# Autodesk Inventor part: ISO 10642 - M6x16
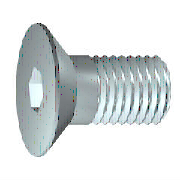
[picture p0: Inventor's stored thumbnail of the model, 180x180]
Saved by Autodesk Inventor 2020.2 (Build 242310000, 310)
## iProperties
Created: 2019-01
Part Number: ISO 10642 - M6x16
Material: Stahl, weich
Description: Senkschrauben mit Innensechskant
Document SubType Name: Modeling
Standard: ISO 10642
Designer: lutzd
Standards Organization: ISO
Language: de-DE
Size Designation: M6x16
Categories: <MemberInstance><Categories><Category DisplayName="Verbindungselemente" InternalName="e4da775c-781d-43d5-af7c-5136215cf5a6" Mnemonic="FSTN"><Category DisplayNam
Mass: 4.34972 g
Surface Area: 5.4059 cm^2
Volume: 0.554104 cm^3
Density: 7.85 g/cm^3
Appearance: Semi-Polished(8)
IsCustomPart: 0
Author: lutzd
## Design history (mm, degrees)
node "WorkPoint1"
sketch "Skizze2"
  geometry: L1 (-3, -16)-(0, -16); L2 (-3, -3.3)-(-3, -16); L3 (-6, -0.3)-(-3, -3.3); L4 (-6, 0)-(-6, -0.3); L5 (0, 0)-(-6, 0); L6 (0, -16)-(0, 0); L7 (0, -16)-(0, 0); L8 (0, -19.2)-(0, 3.2) reference; L9 (1.2, 0)-(-7.2, 0) reference
  constraints: 14 end point, 3 vertical, 2 horizontal
  dimensions: "d3" = 6 distance of L5.start L4.start (= 0.5 x dk); "d5" = 3 distance of L1.start L1.end (= 0.5 x NND); "d7" = 16 distance of L1.end L5.start (= NLG); "ParC" = 0.3 distance of L4.start L3.start; "d22" = 0 distance between parallel lines of L8 L6; "d23" = 0 distance between parallel lines of L9 L5; "d43" = 45 deg angle of L6 L3 (= 0.5 x ang)
revolve "Drehung1" stored, may be unused: angle "d8" = 360 deg
node "MSC_A1"
node "MSC_PF1"
node "MSC_PT1"
body "Solid1"
node "Skizze1"
sketch "Skizze3"
  geometry: L1 (-2, 1.155)-(-2, -1.155); L2 (0, 2.309)-(-2, 1.155); L3 (2, 1.155)-(0, 2.309); L4 (2, -1.155)-(2, 1.155); L5 (0, -2.309)-(2, -1.155); L6 (-2, -1.155)-(0, -2.309); C1 r 2 at (0, 0); C2 r 3 at (0, 0) reference
  constraints: 12 end point, 6 tangent, 2 parallel, 2 vertical, 1 centre point, 1 concentric
  dimensions: "d11" = 4 diameter of C1 (= ParS); "d13" = 120 deg angle of L1 L2; "d15" = 120 deg angle of L6 L1
extrude "Extrusion1" cut sketch "Skizze3" distance "d16" = 2.5 (= ParT); taper "d17" = 0 deg
fillet "Rundung1" dims "d18" = 0.3 (= r)
chamfer "Fase1" distance "d19" = 0.5 (= 0.5 x PTC); stored, may be unused: angle "d20" = 45 deg, second distance "d39" = 0.5 (= 0.5 x PTC)
feature "Gewinde1" dims "d35" = 0, "b" = 10.7
other parameters: "NND" = 6 [user parameter; used in 2 equation terms], "PTC" = 1 [user parameter; used in 2 equation terms], "dk" = 12 [user parameter; used in 1 equation term], "ParK" = 3.3 [user parameter], "ParS" = 4 [user parameter; used in 1 equation term], "ParT" = 2.5 [user parameter; used in 1 equation term], "r" = 0.3 [user parameter; used in 1 equation term], "NLG" = 16 [user parameter; used in 1 equation term], "d0" = 45 deg (derived), "d2" = 3 (derived), "d4" = 1.5 (derived), "d6" = 8 (derived), "d9" = 0, "d10" = 2 (derived), "d12" = 120 deg (derived), "d14" = 120 deg (derived), "d37" = 0, "d38" = 0, "d40" = 0, "d41" = 0, "d42" = 0, "ang" = 90 deg [user parameter; used in 1 equation term], "THREADDIA" = 6 (= NND) [user parameter]
